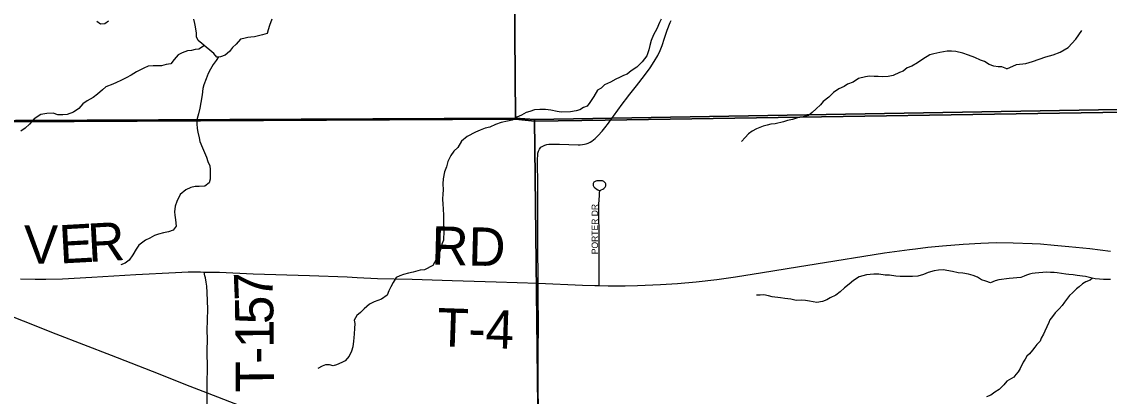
# Model space of a CAD drawing. Extents: x 1985906 to 2360102, y 891258 to 1222054.
# Drawn here: x 2099202 to 2107719, y 1023263 to 1026196 of the extents above; entities that cross this region are included whole.
import ezdxf

# ---------------------------------------------------------------- set-up
doc = ezdxf.new("R2010")
doc.units = 0
for name, color, linetype in [('GM_X_County_Road', 7, 'Continuous'), ('GM_X_Minor_River', 7, 'Continuous'), ('GM_X_Section', 7, 'Continuous'), ('GM_X_Township', 7, 'Continuous'), ('GM_X_Township_Road', 7, 'Continuous'), ('GM_X_Township_Road_Text', 7, 'Continuous'), ('GM_X_Township_Subdivision', 7, 'Continuous'), ('GM_X_Township_Subdivision_Text', 7, 'Continuous'), ('GM_X_US_Route', 7, 'Continuous')]:
    doc.layers.add(name, color=color, linetype=linetype)

msp = doc.modelspace()

# ---------------------------------------------------------------- linework, layer by layer
at = {"layer": 'GM_X_County_Road'}
msp.add_lwpolyline([(2100650.6, 1020950.3), (2100650.4, 1020984.1), (2100650.4, 1021010.3), (2100651.3, 1021097), (2100652.2, 1021229.8), (2100653.7, 1021404.3), (2100654, 1021657), (2100653.2, 1021794.2), (2100653.6, 1021913), (2100653, 1022077.4), (2100652.7, 1022537.6), (2100652.5, 1022708.6), (2100653.4, 1022833.6), (2100653.8, 1022932.1), (2100654.1, 1022981.4), (2100654.2, 1023014.3), (2100654.7, 1023063.5), (2100654.6, 1023211.5), (2100654.3, 1023259), (2100654.2, 1023289.5)], dxfattribs=at)
at = {"layer": 'GM_X_Minor_River'}
for points in [[(2099880.4, 1026199.7), (2099852.5, 1026179.5), (2099818.4, 1026177.3), (2099790.3, 1026197.2)], [(2101160.8, 1026217.6), (2101141, 1026167.3), (2101131.2, 1026133.1), (2101123.3, 1026105), (2101087.3, 1026092.8), (2101055.3, 1026086.6), (2101025.3, 1026078.4), (2100997.2, 1026076.3), (2100971.2, 1026072.2), (2100941.2, 1026066), (2100915.2, 1026059.9), (2100881.3, 1026019.6), (2100853.4, 1025993.3), (2100829.5, 1025963.1), (2100795.6, 1025934.9), (2100757.6, 1025920.6), (2100729.5, 1025918.5), (2100705.3, 1025948.5), (2100675.1, 1025972.4), (2100647, 1025996.4), (2100612.7, 1026026.4), (2100584.6, 1026048.3), (2100570.4, 1026078.4), (2100570.3, 1026106.5), (2100562, 1026156.6), (2100557.8, 1026182.7), (2100549.6, 1026216.8)], [(2104210.7, 1026217.4), (2104196.8, 1026189.3), (2104175, 1026141), (2104149.2, 1026092.7), (2104131.4, 1026050.5), (2104119.6, 1026010.3), (2104113.8, 1025976.1), (2104098, 1025929.9), (2104060.1, 1025881.5), (2104020.3, 1025841.2), (2103974.3, 1025810.9), (2103942.4, 1025786.6), (2103914.4, 1025776.5), (2103884.4, 1025758.3), (2103854.4, 1025746.1), (2103812.5, 1025723.8), (2103766.5, 1025701.5), (2103738.6, 1025677.3), (2103710.6, 1025659.1), (2103682.8, 1025610.8), (2103651, 1025564.5), (2103629.1, 1025536.3), (2103601.1, 1025524.1), (2103573.1, 1025505.9), (2103545.1, 1025499.8), (2103499.1, 1025489.5), (2103427, 1025489.2), (2103394.9, 1025493), (2103346.7, 1025504.9), (2103304.6, 1025508.7), (2103258.5, 1025508.5), (2103218.5, 1025506.3), (2103180.5, 1025492.1), (2103152.4, 1025485.9), (2103116.5, 1025463.7), (2103078.5, 1025449.5), (2103042.5, 1025425.2), (2103006.5, 1025417), (2102956.5, 1025406.7), (2102912.5, 1025390.5), (2102866.5, 1025370.2), (2102832.5, 1025364), (2102792.5, 1025347.8), (2102756.5, 1025331.6), (2102690.5, 1025297.1), (2102646.6, 1025260.8), (2102616.8, 1025212.5), (2102584.9, 1025182.2), (2102561.1, 1025148), (2102539.3, 1025101.7), (2102529.4, 1025059.5), (2102513.6, 1025021.3), (2102501.9, 1024965), (2102500.1, 1024926.9), (2102502.3, 1024878.7), (2102498.5, 1024844.6), (2102496.7, 1024810.4), (2102500.9, 1024764.3), (2102503.1, 1024734.2), (2102505.4, 1024676), (2102505.5, 1024647.9), (2102505.8, 1024601.7), (2102508, 1024557.6), (2102504.4, 1024485.3), (2102492.5, 1024453.1), (2102484.7, 1024416.9), (2102470.8, 1024382.8), (2102451, 1024340.5), (2102421.2, 1024286.2), (2102357.3, 1024253.8), (2102321.2, 1024249.6), (2102267.2, 1024235.3), (2102231.2, 1024227.1)], [(2106917.9, 1025826.3), (2106991.5, 1025861.1), (2107065.4, 1025869.7), (2107117.3, 1025886.1), (2107171.2, 1025902.5), (2107223.1, 1025920.9), (2107278.9, 1025937.3), (2107334.8, 1025957.8), (2107398.5, 1025994.3), (2107456.1, 1026058.8), (2107503.6, 1026127.3)], [(2100632.5, 1026009), (2100588.9, 1025982.1), (2100558.9, 1025977.9), (2100530.9, 1025971.8), (2100498.8, 1025967.6), (2100458.8, 1025953.4), (2100426.8, 1025937.2), (2100395, 1025900.9), (2100369.1, 1025866.7), (2100333.1, 1025860.5), (2100297.1, 1025850.3), (2100263, 1025850.1), (2100230.9, 1025852), (2100192.9, 1025847.8), (2100158.9, 1025833.6), (2100100.9, 1025805.2), (2100059, 1025778.9), (2100019, 1025756.7), (2099979, 1025736.4), (2099945, 1025720.2), (2099915, 1025708), (2099861.1, 1025685.7), (2099833.1, 1025663.5), (2099795.2, 1025629.2), (2099761.3, 1025602.9), (2099715.3, 1025576.6), (2099681.4, 1025554.4), (2099649.5, 1025516.1), (2099607.6, 1025487.8), (2099557.6, 1025469.5), (2099523.5, 1025467.3), (2099485.5, 1025467.2), (2099447.3, 1025481), (2099397.2, 1025478.8), (2099351.2, 1025468.6), (2099299.3, 1025436.2), (2099261.4, 1025393.9), (2099227.5, 1025363.6), (2099195.6, 1025339.4)], [(2100741.5, 1025920.6), (2100723.7, 1025892.4), (2100699.8, 1025862.2), (2100679.9, 1025823.9), (2100662.1, 1025791.7), (2100646.2, 1025749.5), (2100628.4, 1025703.2), (2100620.6, 1025673.1), (2100614.8, 1025622.9), (2100603.1, 1025562.6), (2100595.3, 1025518.4), (2100585.6, 1025474.2), (2100575.7, 1025438), (2100571.9, 1025397.9), (2100576.1, 1025359.7), (2100580.3, 1025331.7), (2100590.5, 1025287.5), (2100596.7, 1025257.4), (2100617, 1025207.4), (2100633.2, 1025173.3), (2100649.4, 1025135.2), (2100659.6, 1025101.2), (2100673.8, 1025067.1), (2100678, 1025039), (2100678.2, 1024998.9), (2100676.4, 1024962.7), (2100670.5, 1024934.6), (2100636.6, 1024908.3), (2100590.5, 1024906.1), (2100560.5, 1024906), (2100526.4, 1024897.8), (2100486.4, 1024879.5), (2100442.5, 1024843.2), (2100416.8, 1024788.9), (2100403, 1024750.7), (2100397.2, 1024708.5), (2100401.3, 1024680.4), (2100405.5, 1024644.3), (2100411.8, 1024594.2), (2100387.9, 1024563.9), (2100349.9, 1024549.7), (2100311.9, 1024543.5), (2100271.8, 1024533.3), (2100241.8, 1024523.1), (2100203.9, 1024500.9), (2100169.9, 1024484.7), (2100120, 1024446.3), (2100098.1, 1024414.1), (2100072.3, 1024371.8), (2100042.5, 1024327.5), (2100012.5, 1024305.3), (2099978.5, 1024291.1)], [(2106917.9, 1025826.3), (2106877.8, 1025842.2), (2106849.7, 1025844), (2106815.6, 1025847.9), (2106777.5, 1025861.8), (2106741.3, 1025883.7), (2106711.2, 1025895.6), (2106667, 1025915.5), (2106616.8, 1025935.3), (2106572.6, 1025951.2), (2106518.4, 1025963), (2106482.4, 1025964.8), (2106450.3, 1025964.7), (2106392.2, 1025956.4), (2106346.2, 1025944.1), (2106314.2, 1025936), (2106260.3, 1025903.6), (2106218.3, 1025875.3), (2106172.4, 1025849), (2106136.4, 1025834.8), (2106104.4, 1025808.5), (2106076.4, 1025798.4), (2106026.5, 1025776.1), (2105986.4, 1025767.8), (2105942.4, 1025763.6), (2105910.3, 1025767.5), (2105878.2, 1025767.3), (2105840.1, 1025769.2), (2105810.1, 1025765), (2105756.1, 1025752.8), (2105714.1, 1025722.4), (2105670.1, 1025708.2), (2105642.2, 1025690), (2105600.2, 1025669.7), (2105558.3, 1025641.4), (2105522.4, 1025605.1), (2105478.5, 1025572.8), (2105458.6, 1025544.6), (2105422.7, 1025514.3), (2105392.7, 1025486.1), (2105362.8, 1025461.9), (2105322.8, 1025451.7), (2105276.7, 1025443.4), (2105238.7, 1025431.2), (2105198.7, 1025423), (2105166.7, 1025412.8), (2105102.7, 1025396.5), (2105068.6, 1025394.3), (2105040.6, 1025386.1), (2105008.6, 1025378), (2104956.6, 1025357.7), (2104922.6, 1025339.4), (2104892.7, 1025317.2), (2104868.8, 1025289), (2104838.9, 1025258.8)], [(2102231.2, 1024227.1), (2102191.2, 1024216.9), (2102163.2, 1024206.7), (2102135.2, 1024192.5), (2102111.3, 1024154.3), (2102093.5, 1024120.1), (2102077.6, 1024087.9), (2102063.8, 1024055.7), (2102019.8, 1024023.4), (2101989.8, 1024013.2), (2101961.8, 1024003), (2101925.9, 1023984.8), (2101884, 1023948.5), (2101856.1, 1023918.2), (2101826.1, 1023896), (2101806.3, 1023859.8), (2101810.4, 1023831.7), (2101808.6, 1023793.6), (2101804.8, 1023751.4), (2101803, 1023721.3), (2101801.1, 1023693.2), (2101795.4, 1023649), (2101785.5, 1023614.8), (2101765.7, 1023576.6), (2101735.8, 1023540.3), (2101707.8, 1023528.1), (2101667.8, 1023509.9), (2101639.8, 1023501.7), (2101611.7, 1023509.6), (2101581.7, 1023509.5), (2101553.7, 1023497.3), (2101521.7, 1023479.1)], [(2106936.4, 1024186.3), (2106854.3, 1024173.9), (2106824.3, 1024165.8), (2106790.3, 1024151.5), (2106752.2, 1024163.4), (2106718.1, 1024175.3), (2106685.9, 1024195.2), (2106653.8, 1024209.1), (2106617.7, 1024219), (2106571.5, 1024226.8), (2106535.4, 1024230.7), (2106491.3, 1024240.5), (2106419.1, 1024252.2), (2106383, 1024250.1), (2106347, 1024245.9), (2106301, 1024231.6), (2106265, 1024217.4), (2106221, 1024203.2), (2106176.9, 1024200.9), (2106082.7, 1024200.5), (2106048.6, 1024204.4), (2105998.5, 1024210.2), (2105964.4, 1024212), (2105914.3, 1024219.8), (2105876.2, 1024219.7), (2105818.2, 1024213.4), (2105790.1, 1024207.2), (2105760.1, 1024197), (2105716.2, 1024168.7), (2105682.3, 1024140.5), (2105646.3, 1024112.2), (2105612.5, 1024079.9), (2105576.5, 1024053.7), (2105534.5, 1024033.4), (2105506.6, 1024019.2), (2105472.6, 1024005), (2105428.5, 1023996.8), (2105372.4, 1024006.6), (2105340.3, 1024012.4), (2105308.2, 1024014.3), (2105266.1, 1024014.1), (2105224, 1024024), (2105177.9, 1024027.8), (2105143.8, 1024033.6), (2105079.6, 1024041.4), (2105049.5, 1024049.3), (2105013.4, 1024057.1), (2104985.4, 1024055), (2104955.3, 1024054.9)], [(2107728.5, 1024176.1), (2107704.3, 1024177.8), (2107674.2, 1024177.4), (2107642.1, 1024179), (2107609.9, 1024182.5), (2107585.7, 1024188.2), (2107563.6, 1024192), (2107533.4, 1024199.6), (2107509.2, 1024203.3), (2107489.1, 1024205), (2107469, 1024208.7), (2107436.8, 1024214.3), (2107402.6, 1024215.9), (2107378.5, 1024219.6), (2107346.3, 1024223.2), (2107310.1, 1024228.7), (2107287.9, 1024232.4), (2107257.8, 1024232), (2107227.7, 1024233.6), (2107197.6, 1024233.2), (2107167.5, 1024230.8), (2107139.4, 1024226.4), (2107115.4, 1024224.1), (2107095.3, 1024219.8), (2107071.3, 1024211.4), (2107051.4, 1024203.2), (2107025.4, 1024192.8), (2106936.4, 1024186.3)], [(2107587.6, 1024187.8), (2107569.9, 1024172), (2107535.9, 1024159.5), (2107510, 1024143.1), (2107484.2, 1024120.7), (2107462.3, 1024104.4), (2107430.6, 1024073.8), (2107408.8, 1024051.5), (2107369.3, 1023998.8), (2107349.5, 1023974.5), (2107325.8, 1023948.1), (2107296.1, 1023915.6), (2107274.3, 1023887.3), (2107254.6, 1023860.9), (2107244.8, 1023840.7), (2107213.6, 1023772.1), (2107203.8, 1023749.9), (2107186.2, 1023717.6), (2107178.5, 1023693.4), (2107152.7, 1023667), (2107136.9, 1023646.8), (2107117.1, 1023624.4), (2107093.4, 1023596), (2107073.6, 1023575.7), (2107059.8, 1023553.5), (2107046, 1023529.2), (2107022.6, 1023480.8), (2107006.8, 1023454.5), (2106987.1, 1023432.2), (2106971.3, 1023411.9)], [(2106971.3, 1023411.9), (2106916.6, 1023381.3), (2106892.7, 1023353.1), (2106856.8, 1023316.8), (2106822.8, 1023294.5), (2106790.9, 1023270.3), (2106758.9, 1023258.1)]]:
    msp.add_lwpolyline(points, dxfattribs=at)
at = {"layer": 'GM_X_Section'}
for points in [[(2108603.7, 1030930.8), (2108603.9, 1030894.8), (2108547.5, 1025523.2), (2103217.8, 1025431.7), (2103067.7, 1025441), (2103026, 1030725.8)], [(2103026, 1030725.8), (2103067.7, 1025441), (2098032.8, 1025418.6), (2097644.6, 1025416.7), (2097619, 1030699.6)], [(2108547.5, 1025523.2), (2108534.6, 1020234.1), (2103278.8, 1020259), (2103217.8, 1025431.7)], [(2103067.7, 1025441), (2103217.8, 1025431.7), (2103278.8, 1020259), (2098003.5, 1020315.5), (2098032.8, 1025418.6)]]:
    msp.add_lwpolyline(points, close=True, dxfattribs=at)
at = {"layer": 'GM_X_Township'}
for points in [[(2108590.2, 1057156.5), (2108639.5, 1052043.3), (2108637.1, 1049741.1), (2108630.4, 1047484.6), (2108627.5, 1046838.9), (2108612.5, 1046641.2), (2108630.4, 1044190.7), (2108630.3, 1044082.6), (2108629.3, 1041511.6), (2108630.8, 1034179.2), (2108627, 1033545.8), (2108551.5, 1029433), (2108528.9, 1027031.5), (2108514.5, 1025497.4), (2103772.2, 1025425.9), (2103219.4, 1025417.6), (2103068.8, 1025432.7), (2097635.3, 1025405.6), (2096078.3, 1025395), (2095094.6, 1025388.3), (2092097.4, 1025367.8)], [(2092097.4, 1025367.8), (2095094.6, 1025388.3), (2096078.3, 1025395), (2097635.3, 1025405.6), (2103068.8, 1025432.7), (2103219.4, 1025417.6), (2103772.2, 1025425.9), (2108514.5, 1025497.4), (2108514.7, 1024273), (2108515.5, 1020728.6), (2108516.1, 1018164.4), (2108516.1, 1017976.2), (2108516.2, 1017490.1), (2108516.8, 1014917.1), (2108517.3, 1014690.8), (2108496.3, 1012312.2), (2108481.1, 1010602), (2108488.7, 1009238.5)]]:
    msp.add_lwpolyline(points, dxfattribs=at)
at = {"layer": 'GM_X_Township_Road'}
for points in [[(2103949.1, 1025608.6), (2103954.4, 1025615.4), (2104016.2, 1025694.3), (2104079.5, 1025776.4), (2104122.5, 1025834.3), (2104156.1, 1025884.3), (2104182.7, 1025931.2), (2104201.5, 1025971), (2104216.4, 1026010.1), (2104236.7, 1026068.7), (2104256.3, 1026130.3), (2104281.3, 1026190.4), (2104288.8, 1026205.1)], [(2103820.9, 1025434.8), (2103835.4, 1025456.2), (2103903.6, 1025550.5), (2103949.1, 1025608.6)], [(2103245.7, 1024147.4), (2103245.2, 1024241.4), (2103244.4, 1024371.1), (2103244.7, 1024501.2), (2103244.5, 1024599.5), (2103244.5, 1024781.5), (2103244.7, 1024877.8), (2103242.6, 1024987.4), (2103242, 1025034.8), (2103240.7, 1025119.2), (2103242.6, 1025150), (2103244.5, 1025166.8), (2103248.8, 1025183.5), (2103256.2, 1025199.2), (2103267.5, 1025212.7), (2103281.8, 1025223), (2103297.4, 1025229.9), (2103313.8, 1025234), (2103330.5, 1025236.2), (2103363.6, 1025237.4), (2103412.9, 1025236.5), (2103560.2, 1025232.2), (2103576.4, 1025232.5), (2103592.4, 1025233.7), (2103608.2, 1025236.1), (2103623.5, 1025240.3), (2103638.4, 1025245.8), (2103652.8, 1025252.6), (2103666.7, 1025261.4), (2103680.8, 1025272.3), (2103692.5, 1025282.5), (2103715.2, 1025304.3), (2103746.7, 1025339.9), (2103768, 1025364.7), (2103798.3, 1025402.8), (2103820.9, 1025434.8)], [(2103722.8, 1024130.8), (2103795.1, 1024128.9), (2103926.5, 1024127.2), (2104025, 1024129.2), (2104205.3, 1024137.5), (2104336.4, 1024146.4), (2104483.5, 1024159.9), (2104646.5, 1024178.2), (2104792.9, 1024198.2), (2105003.5, 1024232.2), (2105278.6, 1024277.1), (2105570, 1024323.7), (2105796.7, 1024360.2), (2105958.7, 1024385.6), (2106153.4, 1024412.4), (2106201.3, 1024417.6), (2106298.6, 1024429.6), (2106412.7, 1024441.6), (2106576.2, 1024453.9), (2106713.6, 1024461.8), (2106834.3, 1024466.1), (2106966.3, 1024464.4), (2107116.1, 1024458.5), (2107180.6, 1024455.9), (2107287.6, 1024446.9), (2107401.3, 1024436.5), (2107566.3, 1024419.1), (2107729.5, 1024400)], [(2099191.8, 1024183.8), (2099306.8, 1024179.7), (2099389.1, 1024179.3), (2099520.6, 1024183.8), (2099750.3, 1024196.5), (2100094.4, 1024215.5), (2100406.1, 1024232.7), (2100504.3, 1024237), (2100602.7, 1024236.6), (2100630.7, 1024236)], [(2100630.7, 1024236), (2100750.3, 1024234.1), (2101012.9, 1024223), (2101456.3, 1024208.1), (2101751.2, 1024198.2), (2101828.4, 1024193.1), (2101988.2, 1024186.2), (2102117.6, 1024183.5), (2102258.3, 1024180), (2102572.8, 1024169.8), (2102917.1, 1024159.9), (2103245.7, 1024147.4)], [(2100654.2, 1023289.5), (2100653.8, 1023368.2), (2100655.5, 1023483.2), (2100654.5, 1023614.7), (2100655.5, 1023713.1), (2100655.1, 1023778.9), (2100657.9, 1023944.1), (2100655.1, 1024074.7), (2100651.4, 1024124.1), (2100646.7, 1024156.9), (2100639.9, 1024190.6), (2100636.9, 1024205.5), (2100630.7, 1024236)], [(2103245.7, 1024147.4), (2103594.6, 1024133.3), (2103690.1, 1024130.9), (2103722.8, 1024130.8)], [(2103256.7, 1022125.2), (2103256.9, 1022308.7), (2103255, 1022438.9), (2103251.1, 1022637.5), (2103250.4, 1022749.3), (2103248.8, 1022886), (2103248.9, 1023047), (2103248.9, 1023120.5), (2103248.1, 1023196.3), (2103246.6, 1023293.3), (2103247.4, 1023391.8), (2103246.6, 1023584.8), (2103247.7, 1023845.4), (2103245.9, 1024025.8), (2103245.7, 1024147.4)]]:
    msp.add_lwpolyline(points, dxfattribs=at)
at = {"layer": 'GM_X_Township_Subdivision'}
msp.add_lwpolyline([(2103722.8, 1024130.8), (2103723.8, 1024221.7), (2103724.3, 1024320.3), (2103723.5, 1024418.8), (2103723.5, 1024566.2), (2103722.3, 1024656), (2103722.3, 1024768), (2103724.1, 1024800.2), (2103725.9, 1024835.9), (2103725.4, 1024852.6), (2103726.2, 1024857.9), (2103727.1, 1024862), (2103729.8, 1024868.9), (2103732.4, 1024873.4), (2103736.5, 1024876.8), (2103740.1, 1024879.2), (2103751.7, 1024884.8), (2103761.1, 1024890.9), (2103766.5, 1024895.6), (2103771.1, 1024901.2), (2103773.9, 1024907), (2103775.4, 1024911.1), (2103776.5, 1024915.7), (2103776.3, 1024921.1), (2103775.2, 1024926.3), (2103773.4, 1024930.7), (2103770.7, 1024935.7), (2103766.5, 1024940.1), (2103761.5, 1024943.8), (2103756.1, 1024946.6), (2103749, 1024948.9), (2103736.5, 1024949.8), (2103716.3, 1024950.2), (2103707.1, 1024949.8), (2103697, 1024948), (2103692.4, 1024946), (2103686.7, 1024942.8), (2103682.1, 1024938.6), (2103679.4, 1024933.7), (2103677.5, 1024929.1), (2103676.5, 1024924.2), (2103676.5, 1024919.8), (2103677.5, 1024914.1), (2103679.6, 1024908.1), (2103682.5, 1024903.4), (2103687.4, 1024897.3), (2103694.6, 1024891.8), (2103700.9, 1024888.2), (2103713, 1024880.3), (2103728.2, 1024871)], dxfattribs=at)
at = {"layer": 'GM_X_US_Route'}
msp.add_lwpolyline([(2098953.6, 1023954.4), (2099469.3, 1023750.9), (2099900.8, 1023584), (2100269.6, 1023440.3), (2100482.9, 1023355.9), (2100654.2, 1023289.5), (2101339.7, 1023023.5), (2101586.1, 1022925.7), (2101828.9, 1022832.8), (2102119, 1022718.9), (2102301, 1022644), (2102421.1, 1022591.4), (2102554.8, 1022528.8), (2102685.4, 1022462.6), (2102788.3, 1022409.6), (2102915.7, 1022338.6), (2103043.5, 1022262.1), (2103155.2, 1022192.7), (2103232.4, 1022141.2), (2103256.7, 1022125.2)], dxfattribs=at)

# ---------------------------------------------------------------- texts
at = {"layer": 'GM_X_Township_Road_Text'}
for s, rotation, p in [('V', 0.19801, (2099220.8, 1024300.6)), ('E', 3.13984, (2099501.7, 1024302)), ('R', 3.20204, (2099726.1, 1024314.3)), ('RD', 358.51843, (2102407.2, 1024295.2)), ('7', 92.39345, (2101170.6, 1024022.2)), ('5', 90.99818, (2101174.1, 1023829.4)), ('T-4', 358.05352, (2102451.6, 1023654.7)), ('1', 90.51997, (2101175.8, 1023641.9)), ('-', 90.39096, (2101176.7, 1023518)), ('T', 90.35786, (2101178.1, 1023293.4))]:
    msp.add_text(s, height=300, rotation=rotation, dxfattribs=at).set_placement(p)
at = {"layer": 'GM_X_Township_Subdivision_Text'}
msp.add_text('PORTER DR', height=50, rotation=90, dxfattribs=at).set_placement((2103714.8, 1024375.3))

doc.saveas('drawing.dxf')
